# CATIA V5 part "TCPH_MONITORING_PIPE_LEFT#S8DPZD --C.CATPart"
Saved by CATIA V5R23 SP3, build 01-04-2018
Part number: TCPH_MONITORING_PIPE_LEFT#S8DPYV
Revision: --C
Nomenclature: _
Description: TCPH_MONITORING_PIPE_LEFT
Property "ID": "S8DPYV"
Property "AT": "PD"
Property "REP": "CM"
Property "External Part ID": "_"
Property "PREF": "Y"
Property "LONG": "_"
Property "PBS 1": "24"
Property "PBS 2": "CR"
Property "PBS 3": "LC"
Property "DEPT": "_"
Property "DIVN": "_"
Property "GROUP": "_"
Property "UNIT": "_"
Property "PARTY": "_"
Property "RO": "IOKIK"
Property "RE": "VITUPIG"
Property "PRO": "---"
Property "Change Type": "Minor"
Property "Maturity Level": "CD"
Property "Export Number": "_"
Property "Description Modification": "_"
Property "Description Documents": "_"
Property "BOM": "_"
Property "User In Enovia": "BLANCHA"
Property "Object Type": "_"
Property "CADENAS_ID": "_"
Property "Life Cycle Status": "Approved"
Material "X2CrNi18-09 1.4307 (304L)": density 8000 kg/m3, Young's modulus 1.93e+11 Pa, Poisson ratio 0.3, thermal expansion 1.6e-05 1/K
Bounding box of the stored display mesh (mm): x 13037 to 14145, y -993 to -685, z -4396 to -3360
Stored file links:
  C:\Users\pandeym\Desktop\__TCPH\TCPH_MONITORING_PIPE_LEFT#S8DPZD --C.CATPart
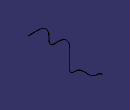
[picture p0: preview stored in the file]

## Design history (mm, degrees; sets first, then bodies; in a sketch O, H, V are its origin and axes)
Set1
  DatumCurve1 "MONITORING_PIPE_PROFIL": linked copy from another document
  Sketch1 "MONITORING_PIPE_SECTION", origin (0, 685, 0), H (-1, 0, 0), V (0, 0, 1), geometry linked from another document
Set2
  Symmetry1: ToTransfor DatumCurve1, Reference zx-plane
  Symmetry2: ToTransfor Sketch1, Reference zx-plane
Body1 (main body)
  Rib1: profile Symmetry2, centre curve Symmetry1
